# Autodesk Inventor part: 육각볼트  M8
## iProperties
Created: 2009-02
Part Number: 육각볼트  M8
Material: 강, 연강
Description: 6각 머리 볼트 및 6각 머리 나사
Document SubType Name: Modeling
Standard: KS B 1002
Designer: SeoGD™[esajin.kr]
Standards Organization: KS
Language: ko-KR
Size Designation: C  M 8 x 40
Categories: <MemberInstance><Categories><Category DisplayName="조임쇠" InternalName="e4da775c-781d-43d5-af7c-5136215cf5a6" Mnemonic="FSTN"><Category DisplayName="볼트" InternalN
Density: 1 g/cm^3
IsCustomPart: 1
Author: SeoGD™[esajin.kr]
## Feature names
1. Fillet2
